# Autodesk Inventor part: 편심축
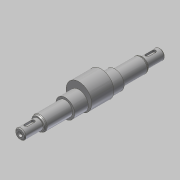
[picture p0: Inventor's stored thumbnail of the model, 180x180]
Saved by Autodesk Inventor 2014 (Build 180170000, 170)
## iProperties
Created: 2019-01
Part Number: 편심축
Material: 강철, 연강
Document SubType Name: Modeling
Designer: mduedu
Density: 1 g/cm^3
Appearance: 강철
Author: mduedu
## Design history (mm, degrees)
sketch "스케치1"
  geometry: L1 (0, 0)-(21, 0); L2 (21, 0)-(21, 6); L3 (21, 6)-(0, 6); L4 (0, 6)-(0, 0); L5 (21, 0)-(53, 0); L6 (53, 0)-(53, 8.5); L7 (53, 8.5)-(21, 8.5); L8 (21, 8.5)-(21, 0); L9 (53, 0)-(111, 0); L10 (111, 0)-(111, 11); L11 (111, 11)-(53, 11); L12 (53, 11)-(53, 0); L13 (82, 11)-(82, 0); L14 (111, 0)-(143, 0); L15 (143, 0)-(143, 8.5); L16 (143, 8.5)-(111, 8.5); L17 (111, 8.5)-(111, 0); L18 (143, 0)-(164, 0); L19 (164, 0)-(164, 6); L20 (164, 6)-(143, 6); L21 (143, 6)-(143, 0)
  constraints: 42 end point, 10 parallel, 5 horizontal, 5 perpendicular, 4 collinear, 2 midpoint
  dimensions: "d3" = 58 distance of L10.end L11.end; "d5" = 12 diameter of L3 L1; "d6" = 17 diameter of L7 L5; "d8" = 22 diameter of L11 L9; "d51" = 164 distance between parallel lines of L4 L19; "d52" = 122 distance between parallel lines of L2 L15; "d53" = 32 distance of L15.end L16.end (derived); "d54" = 32 distance of L6.end L7.end (derived)
revolve "회전1" sketch "스케치1" stored, may be unused: angle "d9" = 90 deg
node "작업 평면3"
sketch "스케치2"
  geometry: C1 r 15 at (0, 4); C2 r 11 at (0, 0); 1 further point
  constraints: 2 centre point, 1 tangent, 1 vertical alignment
  dimensions: "d11" = 4 distance of point (0, 0) C1.centre
extrude "돌출1" join sketch "스케치2" distance "d12" = 26; taper "d13" = 0 deg
node "작업 평면2"
sketch "스케치3" dims "d16" = 12
  geometry: L1 (-4.5, 2)-(3.5, 2); L2 (3.5, 2)-(3.5, -2); L3 (3.5, -2)-(-4.5, -2); L4 (-4.5, -2)-(-4.5, 2); L5 (-10.5, 8.5)-(-10.5, -8.5) reference; 3 further points
  constraints: 8 end point, 2 midpoint, 2 parallel, 2 vertical alignment, 1 horizontal, 1 horizontal alignment, 1 perpendicular, 4 other
  dimensions: "d14" = 4 distance between parallel lines of L3 L1; "d17" = 4 dimension on L5
extrude "돌출2" cut sketch "스케치3" distance "d18" = 2.5; taper "d19" = 0 deg
node "작업 평면4"
chamfer "모따기1" distance "d20" = 1.82; stored, may be unused: second distance "d21" = 2, angle "d22" = 30 deg
chamfer "모따기3" distance "d56" = 1.82; stored, may be unused: second distance "d57" = 2, angle "d58" = 30 deg
fillet "모깎기1" dims "d23" = 2
hole "구멍2" diameter "d39" = 3.242; stored, may be unused: countersink angle "d43" = 60 deg, drill point angle "d45" = 118 deg; dims "d37" = 10, "d38" = 10, "d40" = 8, "d41" = 5.51, "d42" = 2, "d44" = 10
sketch "스케치5"
  geometry: L1 (0, 0)-(2, 0); L2 (2, 0)-(2, 1.621); L3 (0, 2.776)-(0, 0); L4 (0, 2.776)-(2, 1.621); L5 (10, 1.621)-(0, 1.621) reference
  constraints: 8 end point, 1 horizontal, 1 parallel, 1 perpendicular, 1 point on line
  dimensions: "d46" = 2 distance between parallel lines of L2 L3; "d48" = 30 deg angle of L4 L1
revolve "회전2" sketch "스케치5" stored, may be unused: angle "d50" = 90 deg
chamfer "모따기2" distance "d25" = 1; stored, may be unused: second distance "d26" = 2, angle "d27" = 30 deg
node "솔리드1"
mirror "대칭1"
mirror "대칭2"
mirror "대칭3"
other parameters: "d55" = -16
